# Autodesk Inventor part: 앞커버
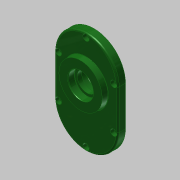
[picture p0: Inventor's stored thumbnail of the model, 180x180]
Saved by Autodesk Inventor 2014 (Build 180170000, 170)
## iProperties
Created: 2016-12
Part Number: 앞커버
Material: 일반
Document SubType Name: Modeling
Designer: mduedu
Density: 1 g/cm^3
Appearance: 매끄러움 - 짙은 산림 녹색
Mass: 97.664 g
Surface Area: 264.413 cm^2
Volume: 97.664 cm^3
Author: mduedu
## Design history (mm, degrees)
sketch "스케치1"
  geometry: L1 (40, -25)-(40, 25); L2 (-40, 25)-(-40, -25); L3 (-40, -25)-(40, 25); L4 (40, -25)-(-40, 25); A1 r 40 centre (0, 25) between (40, 25) and (-40, 25); A2 r 40 centre (0, -25) between (-40, -25) and (40, -25); 1 further point
  constraints: 8 end point, 4 point on circle, 4 tangent, 2 centre point, 2 midpoint, 1 parallel, 1 vertical
  dimensions: "d0" = 130 dimension on A2 A1; "d2" = 80 distance between parallel lines of L1 L2
extrude "돌출1" new body sketch "스케치1" distance "d3" = 10; taper "d4" = 0 deg
sketch "스케치2"
  geometry: C1 r 21 at (0, 11); 1 further point
  constraints: 1 centre point, 1 vertical alignment
  dimensions: "d5" = 42 diameter of C1; "d7" = 11 distance of C1.centre point (0, 0)
extrude "돌출2" join sketch "스케치2" distance "d8" = 7; taper "d9" = 0 deg
sketch "스케치3"
  geometry: C1 r 15 at (0, -33.1); C2 r 21 at (0, 11) reference; 1 further point
  constraints: 1 centre point, 1 vertical alignment
  dimensions: "d10" = 30 diameter of C1; "d71" = 44.1 distance of C1.centre C2.centre
extrude "돌출3" join sketch "스케치3" distance "d12" = 7; taper "d13" = 0 deg
sketch "스케치4"
  geometry: C1 r 28 at (0, 11); A1 r 21 centre (0, 11) between (8.978, -7.984) and (-8.978, -7.984) reference; 1 further point
  constraints: 1 centre point, 1 coincident
  dimensions: "d14" = 56 diameter of C1
extrude "돌출4" join sketch "스케치4" distance "d15" = 7; taper "d16" = -5 deg
hole "구멍1" diameter "d19" = 35; stored, may be unused: countersink angle "d23" = 90 deg, drill point angle "d25" = 0 deg; dims "d17" = 10, "d18" = 10, "d20" = 6, "d21" = 4, "d22" = 2, "d24" = 10
hole "구멍2" diameter "d28" = 22; stored, may be unused: countersink angle "d32" = 90 deg, drill point angle "d34" = 0 deg; dims "d26" = 10, "d27" = 10, "d29" = 6, "d30" = 4, "d31" = 2, "d33" = 7
hole "구멍3" diameter "d37" = 19; stored, may be unused: countersink angle "d41" = 90 deg, drill point angle "d43" = 0 deg; dims "d35" = 10, "d36" = 10, "d38" = 6, "d39" = 4, "d40" = 2, "d42" = 1
hole "구멍4" diameter "d46" = 32; stored, may be unused: countersink angle "d50" = 90 deg, drill point angle "d52" = 0 deg; dims "d47" = 6, "d48" = 4, "d49" = 2, "d51" = 8.3, "d89" = 10, "d90" = 10
hole "구멍5" diameter "d55" = 25; stored, may be unused: countersink angle "d59" = 90 deg, drill point angle "d61" = 0 deg; dims "d53" = 10, "d54" = 10, "d56" = 6, "d57" = 4, "d58" = 2, "d60" = 8
fillet "모깎기1" dims "d62" = 0.3
fillet "모깎기2" dims "d63" = 2
chamfer "모따기1" distance "d64" = 1; stored, may be unused: second distance "d65" = 2, angle "d66" = 45 deg
chamfer "모따기2" distance "d91" = 0.8; stored, may be unused: second distance "d92" = 2, angle "d93" = 30 deg
fillet "모깎기4" dims "d68" = 2
fillet "모깎기5" dims "d69" = 0.3
fillet "모깎기6" dims "d70" = 2
sketch "스케치5"
  geometry: L1 (-40, 25)-(-40, -25) reference; L2 (40, -25)-(40, 25) reference; L3 (35, 25)-(35, -25); L4 (-35, -25)-(-35, 25); A1 r 40 centre (0, 25) between (40, 25) and (-40, 25) reference; A2 r 40 centre (0, -25) between (-40, -25) and (40, -25) reference; A3 r 35 centre (0, 25) between (35, 25) and (-35, 25); A4 r 35 centre (0, -25) between (-35, -25) and (35, -25); 2 further points
  constraints: 5 point on circle, 4 end point, 2 centre point, 1 vertical alignment, 3 other
  dimensions: "d72" = 5 distance between parallel lines of L2 L3
sketch "스케치7"
  geometry: 1 further point
  constraints: 1 other
hole "구멍7" sketch "스케치7" at (0, 60) diameter "d80" = 4.5; stored, may be unused: countersink angle "d84" = 90 deg, drill point angle "d86" = 0 deg; dims "d81" = 6, "d82" = 8, "d83" = 4.6, "d85" = 8
node "솔리드1"
pattern_linear "직사각형 패턴1"
